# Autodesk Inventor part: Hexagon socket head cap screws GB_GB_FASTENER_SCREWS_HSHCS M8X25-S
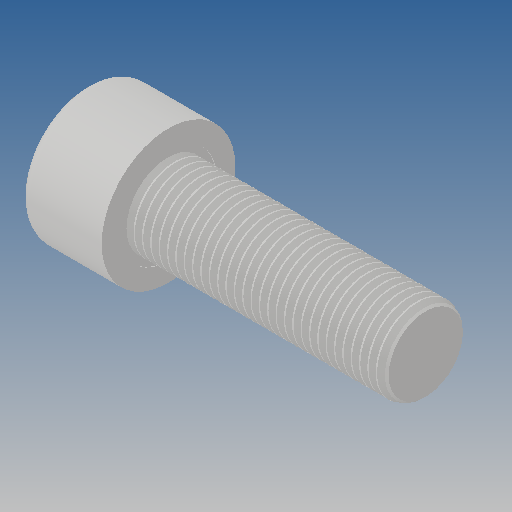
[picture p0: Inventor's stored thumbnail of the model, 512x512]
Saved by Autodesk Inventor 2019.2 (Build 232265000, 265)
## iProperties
Created: 2013-09
Part Number: Hexagon socket head cap screws GB_GB_FASTENER_SCREWS_HSHCS M8X25-S
Material: Ogólny
Document SubType Name: Modeling
Designer: CADENGINEERING4
Density: 1 g/cm^3
Appearance: Domyślna
Author: CADENGINEERING4
Revision Number: ÈÎºÎ
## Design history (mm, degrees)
feature "LPattern10"
node "Bryła1"
